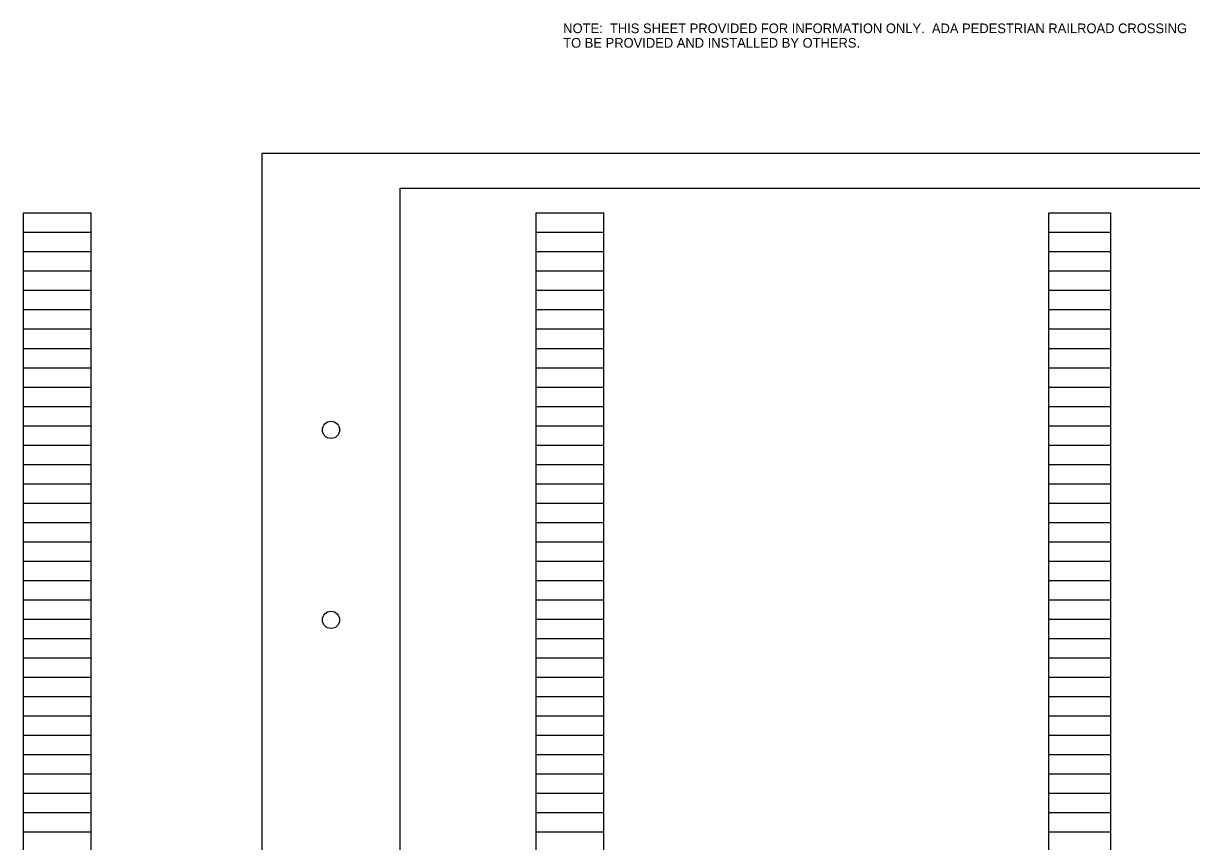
# Model space of a CAD drawing. Extents: x 30 to 362, y -13 to 11.
# Drawn here: x 86.05 to 102.96, y -0.87 to 10.98 of the extents above; entities that cross this region are included whole.
import ezdxf

# ---------------------------------------------------------------- set-up
doc = ezdxf.new("R2010")
doc.units = 0
for name, color, linetype in [('SH_Border', 7, 'Continuous'), ('SH_Cut_Line', 7, 'Continuous'), ('SH_Data', 7, 'Continuous'), ('TX_P_1', 7, 'Continuous')]:
    doc.layers.add(name, color=color, linetype=linetype)

msp = doc.modelspace()

# ---------------------------------------------------------------- linework, layer by layer
at = {"layer": 'SH_Border'}
msp.add_lwpolyline([(91.502, 8.593), (123.002, 8.593), (123.002, -12.407), (91.502, -12.407)], close=True, dxfattribs=at)
for centre in [(90.502, 5.093), (90.502, 2.343)]:
    msp.add_circle(centre, 0.125, dxfattribs=at)
at = {"layer": 'SH_Cut_Line'}
msp.add_lwpolyline([(89.502, -12.907), (123.502, -12.907), (123.502, 9.093), (89.502, 9.093)], close=True, dxfattribs=at)
at = {"layer": 'SH_Data'}
for p, q in [((86.05, -11.927), (86.05, 8.233)), ((86.05, 8.233), (87.03, 8.233)), ((87.03, -11.927), (87.03, 8.233)), ((93.47, -11.927), (93.47, 8.233)), ((93.47, 8.233), (94.45, 8.233)), ((94.45, -11.927), (94.45, 8.233)), ((100.89, -11.927), (100.89, 8.233)), ((100.89, 8.233), (101.79, 8.233)), ((101.79, -11.927), (101.79, 8.233)), ((86.05, 7.953), (87.03, 7.953)), ((93.47, 7.953), (94.45, 7.953)), ((100.89, 7.953), (101.79, 7.953)), ((86.05, 7.673), (87.03, 7.673)), ((93.47, 7.673), (94.45, 7.673)), ((100.89, 7.673), (101.79, 7.673)), ((86.05, 7.393), (87.03, 7.393)), ((93.47, 7.393), (94.45, 7.393)), ((100.89, 7.393), (101.79, 7.393)), ((86.05, 7.113), (87.03, 7.113)), ((93.47, 7.113), (94.45, 7.113)), ((100.89, 7.113), (101.79, 7.113)), ((86.05, 6.833), (87.03, 6.833)), ((93.47, 6.833), (94.45, 6.833)), ((100.89, 6.833), (101.79, 6.833)), ((86.05, 6.553), (87.03, 6.553)), ((93.47, 6.553), (94.45, 6.553)), ((100.89, 6.553), (101.79, 6.553)), ((86.05, 6.273), (87.03, 6.273)), ((93.47, 6.273), (94.45, 6.273)), ((100.89, 6.273), (101.79, 6.273)), ((86.05, 5.993), (87.03, 5.993)), ((93.47, 5.993), (94.45, 5.993)), ((100.89, 5.993), (101.79, 5.993)), ((86.05, 5.713), (87.03, 5.713)), ((93.47, 5.713), (94.45, 5.713)), ((100.89, 5.713), (101.79, 5.713)), ((86.05, 5.433), (87.03, 5.433)), ((93.47, 5.433), (94.45, 5.433)), ((100.89, 5.433), (101.79, 5.433)), ((86.05, 5.153), (87.03, 5.153)), ((93.47, 5.153), (94.45, 5.153)), ((100.89, 5.153), (101.79, 5.153)), ((86.05, 4.873), (87.03, 4.873)), ((93.47, 4.873), (94.45, 4.873)), ((100.89, 4.873), (101.79, 4.873)), ((86.05, 4.593), (87.03, 4.593)), ((93.47, 4.593), (94.45, 4.593)), ((100.89, 4.593), (101.79, 4.593)), ((86.05, 4.313), (87.03, 4.313)), ((93.47, 4.313), (94.45, 4.313)), ((100.89, 4.313), (101.79, 4.313)), ((86.05, 4.033), (87.03, 4.033)), ((93.47, 4.033), (94.45, 4.033)), ((100.89, 4.033), (101.79, 4.033)), ((86.05, 3.753), (87.03, 3.753)), ((93.47, 3.753), (94.45, 3.753)), ((100.89, 3.753), (101.79, 3.753)), ((86.05, 3.473), (87.03, 3.473)), ((93.47, 3.473), (94.45, 3.473)), ((100.89, 3.473), (101.79, 3.473)), ((86.05, 3.193), (87.03, 3.193)), ((93.47, 3.193), (94.45, 3.193)), ((100.89, 3.193), (101.79, 3.193)), ((86.05, 2.913), (87.03, 2.913)), ((93.47, 2.913), (94.45, 2.913)), ((100.89, 2.913), (101.79, 2.913)), ((86.05, 2.633), (87.03, 2.633)), ((93.47, 2.633), (94.45, 2.633)), ((100.89, 2.633), (101.79, 2.633)), ((86.05, 2.353), (87.03, 2.353)), ((93.47, 2.353), (94.45, 2.353)), ((100.89, 2.353), (101.79, 2.353)), ((86.05, 2.073), (87.03, 2.073)), ((93.47, 2.073), (94.45, 2.073)), ((100.89, 2.073), (101.79, 2.073)), ((86.05, 1.793), (87.03, 1.793)), ((93.47, 1.793), (94.45, 1.793)), ((100.89, 1.793), (101.79, 1.793)), ((86.05, 1.513), (87.03, 1.513)), ((93.47, 1.513), (94.45, 1.513)), ((100.89, 1.513), (101.79, 1.513)), ((86.05, 1.233), (87.03, 1.233)), ((93.47, 1.233), (94.45, 1.233)), ((100.89, 1.233), (101.79, 1.233)), ((86.05, 0.953), (87.03, 0.953)), ((93.47, 0.953), (94.45, 0.953)), ((100.89, 0.953), (101.79, 0.953)), ((86.05, 0.673), (87.03, 0.673)), ((93.47, 0.673), (94.45, 0.673)), ((100.89, 0.673), (101.79, 0.673)), ((86.05, 0.393), (87.03, 0.393)), ((93.47, 0.393), (94.45, 0.393)), ((100.89, 0.393), (101.79, 0.393)), ((86.05, 0.113), (87.03, 0.113)), ((93.47, 0.113), (94.45, 0.113)), ((100.89, 0.113), (101.79, 0.113)), ((86.05, -0.167), (87.03, -0.167)), ((93.47, -0.167), (94.45, -0.167)), ((100.89, -0.167), (101.79, -0.167)), ((86.05, -0.447), (87.03, -0.447)), ((93.47, -0.447), (94.45, -0.447)), ((100.89, -0.447), (101.79, -0.447)), ((86.05, -0.727), (87.03, -0.727)), ((93.47, -0.727), (94.45, -0.727)), ((100.89, -0.727), (101.79, -0.727))]:
    msp.add_line(p, q, dxfattribs=at)

# ---------------------------------------------------------------- texts
at = {"layer": 'TX_P_1'}
for s, p in [('NOTE:  THIS SHEET PROVIDED FOR INFORMATION ONLY.  ADA PEDESTRIAN RAILROAD CROSSING', (93.863, 10.835)), ('TO BE PROVIDED AND INSTALLED BY OTHERS.', (93.863, 10.625))]:
    msp.add_text(s, height=0.14, dxfattribs=at).set_placement(p)

doc.saveas('drawing.dxf')
